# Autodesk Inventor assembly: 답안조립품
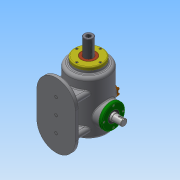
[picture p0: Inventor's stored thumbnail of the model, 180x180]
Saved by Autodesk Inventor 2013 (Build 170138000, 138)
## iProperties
Created: 2017-01
Part Number: 답안조립품
Document SubType Name: Assembly
Designer: Administrator
Author: Administrator
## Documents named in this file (16)
- C:\Users\Administrator\Desktop\370108V1007\답안조립품.iam
- C:\Users\Administrator\Desktop\370108V1007\베어링 6205.ipt
- 베어링 6205.ipt
- C:\Users\Administrator\Desktop\370108V1007\본체.ipt
- C:\Users\Administrator\Desktop\370108V1007\볼트 M4x0.7.ipt
- C:\Users\Administrator\Desktop\370108V1007\부시.ipt
- C:\Users\Administrator\Desktop\370108V1007\상부 캡.ipt
- C:\Users\Administrator\Desktop\370108V1007\슬라이드 커버.ipt
- C:\Users\Administrator\Desktop\370108V1007\슬라이드.ipt
- C:\Users\Administrator\Desktop\370108V1007\오일실.ipt
- 오일실.ipt
- C:\Users\Administrator\Desktop\370108V1007\축 커버-1.ipt
- C:\Users\Administrator\Desktop\370108V1007\축 커버-2.ipt
- C:\Users\Administrator\Desktop\370108V1007\편심축.ipt
- C:\Users\Administrator\Desktop\370108V1007\플레이트.ipt
- C:\Users\Administrator\Desktop\370108V1007\가변스프링.ipt
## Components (14 placed, 3 different names)
1. 플레이트:1 — 각도:1
2. 가변스프링:1
3. M4x0.7:2
4. M4x0.7:4
5. M4x0.7:5
6. M4x0.7:6
7. M4x0.7:1
8. M4x0.7:7
9. M4x0.7:8
10. M4x0.7:9
11. M4x0.7:3
12. M4x0.7:10
13. M4x0.7:11
14. M4x0.7:12
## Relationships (1: Angle 1)
- 각도:1 [Angle]: 플레이트:1
